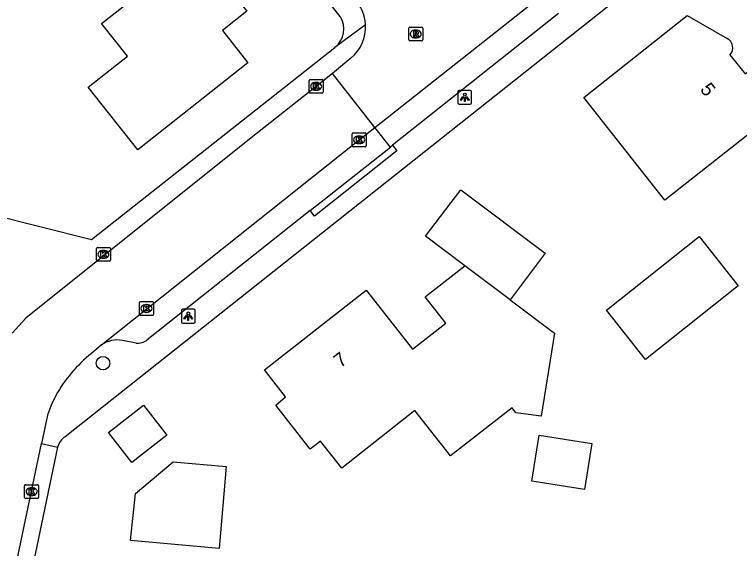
# Model space of a CAD drawing. Extents: x 159628 to 160723, y 388176 to 389416.
# Drawn here: x 159907.8 to 159959.9, y 388591.8 to 388630.2 of the extents above; entities that cross this region are included whole.
import ezdxf

# ---------------------------------------------------------------- set-up
doc = ezdxf.new("R2010")
doc.units = 0
for name, color, linetype in [('IMGEO_Boom', 7, 'Continuous'), ('IMGEO_Kolk', 7, 'Continuous'), ('IMGEO_Lichtpunt', 7, 'Continuous'), ('IMGEO_Pand', 7, 'Continuous'), ('IMGEO_Pand_nummerreeks', 7, 'Continuous'), ('IMGEO_Parkeervlak_open', 7, 'Continuous'), ('IMGEO_Rijbaan_lokaal_open', 7, 'Continuous'), ('IMGEO_Rioolput', 7, 'Continuous'), ('IMGEO_Voetpad_open', 7, 'Continuous')]:
    doc.layers.add(name, color=color, linetype=linetype)

msp = doc.modelspace()

# ---------------------------------------------------------------- linework, layer by layer
at = {"layer": 'IMGEO_Boom'}
msp.add_circle((159914.185, 388605.108), 0.489, dxfattribs=at)
at = {"layer": 'IMGEO_Kolk'}
for p, q in [((159929.006, 388624.603), (159929.006, 388625.455)), ((159929.081, 388625.529), (159929.933, 388625.529)), ((159930.007, 388625.455), (159930.007, 388624.603)), ((159929.494, 388625.309), (159929.519, 388625.309)), ((159929.933, 388624.529), (159929.081, 388624.529)), ((159929.517, 388624.749), (159929.492, 388624.749)), ((159932.102, 388620.76), (159932.102, 388621.612)), ((159932.177, 388621.686), (159933.029, 388621.686)), ((159932.59, 388621.466), (159932.615, 388621.466)), ((159933.103, 388621.612), (159933.103, 388620.76)), ((159933.029, 388620.686), (159932.177, 388620.686)), ((159932.613, 388620.906), (159932.588, 388620.906)), ((159913.713, 388612.516), (159913.713, 388613.368)), ((159913.788, 388613.442), (159914.64, 388613.442)), ((159914.714, 388613.368), (159914.714, 388612.516)), ((159914.201, 388613.222), (159914.226, 388613.222)), ((159914.64, 388612.442), (159913.788, 388612.442)), ((159914.224, 388612.662), (159914.199, 388612.662)), ((159916.81, 388608.621), (159916.81, 388609.473)), ((159916.885, 388609.547), (159917.737, 388609.547)), ((159917.298, 388609.327), (159917.323, 388609.327)), ((159917.811, 388609.473), (159917.811, 388608.621)), ((159917.321, 388608.767), (159917.296, 388608.767)), ((159917.737, 388608.547), (159916.885, 388608.547)), ((159908.55, 388595.44), (159908.55, 388596.292)), ((159908.625, 388596.366), (159909.477, 388596.366)), ((159909.551, 388596.292), (159909.551, 388595.44)), ((159909.038, 388596.146), (159909.063, 388596.146)), ((159909.477, 388595.366), (159908.625, 388595.366)), ((159909.061, 388595.586), (159909.036, 388595.586))]:
    msp.add_line(p, q, dxfattribs=at)
for points in [[(159929.006, 388624.603), (159929.006, 388625.455)], [(159929.081, 388625.529), (159929.933, 388625.529)], [(159930.007, 388625.455), (159930.007, 388624.603)], [(159929.327, 388625.229), (159929.45, 388625.229), (159929.45, 388625.078), (159929.58, 388625.229), (159929.744, 388625.229), (159929.598, 388625.078), (159929.751, 388624.829), (159929.599, 388624.829), (159929.514, 388624.993), (159929.45, 388624.926), (159929.45, 388624.829), (159929.327, 388624.829), (159929.327, 388625.229)], [(159929.933, 388624.529), (159929.081, 388624.529)], [(159932.102, 388620.76), (159932.102, 388621.612)], [(159932.177, 388621.686), (159933.029, 388621.686)], [(159932.423, 388621.386), (159932.546, 388621.386), (159932.546, 388621.235), (159932.676, 388621.386), (159932.84, 388621.386), (159932.694, 388621.235), (159932.847, 388620.986), (159932.695, 388620.986), (159932.61, 388621.15), (159932.546, 388621.083), (159932.546, 388620.986), (159932.423, 388620.986), (159932.423, 388621.386)], [(159933.103, 388621.612), (159933.103, 388620.76)], [(159933.029, 388620.686), (159932.177, 388620.686)], [(159913.713, 388612.516), (159913.713, 388613.368)], [(159913.788, 388613.442), (159914.64, 388613.442)], [(159914.714, 388613.368), (159914.714, 388612.516)], [(159914.034, 388613.142), (159914.157, 388613.142), (159914.157, 388612.991), (159914.287, 388613.142), (159914.451, 388613.142), (159914.305, 388612.991), (159914.458, 388612.742), (159914.306, 388612.742), (159914.221, 388612.906), (159914.157, 388612.839), (159914.157, 388612.742), (159914.034, 388612.742), (159914.034, 388613.142)], [(159914.64, 388612.442), (159913.788, 388612.442)], [(159916.81, 388608.621), (159916.81, 388609.473)], [(159916.885, 388609.547), (159917.737, 388609.547)], [(159917.131, 388609.247), (159917.254, 388609.247), (159917.254, 388609.096), (159917.384, 388609.247), (159917.548, 388609.247), (159917.402, 388609.096), (159917.555, 388608.847), (159917.403, 388608.847), (159917.318, 388609.011), (159917.254, 388608.944), (159917.254, 388608.847), (159917.131, 388608.847), (159917.131, 388609.247)], [(159917.811, 388609.473), (159917.811, 388608.621)], [(159917.737, 388608.547), (159916.885, 388608.547)], [(159908.55, 388595.44), (159908.55, 388596.292)], [(159908.625, 388596.366), (159909.477, 388596.366)], [(159909.551, 388596.292), (159909.551, 388595.44)], [(159908.871, 388596.066), (159908.994, 388596.066), (159908.994, 388595.915), (159909.124, 388596.066), (159909.288, 388596.066), (159909.142, 388595.915), (159909.295, 388595.666), (159909.143, 388595.666), (159909.058, 388595.83), (159908.994, 388595.763), (159908.994, 388595.666), (159908.871, 388595.666), (159908.871, 388596.066)], [(159909.477, 388595.366), (159908.625, 388595.366)]]:
    msp.add_lwpolyline(points, dxfattribs=at)
for centre, start, end in [((159929.083, 388625.453), 91.552, 178.448), ((159929.083, 388625.453), 91.552, 178.448), ((159929.931, 388625.453), 1.552, 88.448), ((159929.931, 388625.453), 1.552, 88.448), ((159929.083, 388624.605), 181.552, 268.448), ((159929.083, 388624.605), 181.552, 268.448), ((159929.931, 388624.605), 271.552, 358.448), ((159929.931, 388624.605), 271.552, 358.448), ((159932.179, 388621.61), 91.552, 178.448), ((159932.179, 388621.61), 91.552, 178.448), ((159933.027, 388621.61), 1.552, 88.448), ((159933.027, 388621.61), 1.552, 88.448), ((159932.179, 388620.762), 181.552, 268.448), ((159932.179, 388620.762), 181.552, 268.448), ((159933.027, 388620.762), 271.552, 358.448), ((159933.027, 388620.762), 271.552, 358.448), ((159913.79, 388613.366), 91.552, 178.448), ((159913.79, 388613.366), 91.552, 178.448), ((159914.638, 388613.366), 1.552, 88.448), ((159914.638, 388613.366), 1.552, 88.448), ((159913.79, 388612.518), 181.552, 268.448), ((159913.79, 388612.518), 181.552, 268.448), ((159914.638, 388612.518), 271.552, 358.448), ((159914.638, 388612.518), 271.552, 358.448), ((159916.887, 388609.471), 91.552, 178.448), ((159916.887, 388609.471), 91.552, 178.448), ((159917.735, 388609.471), 1.552, 88.448), ((159917.735, 388609.471), 1.552, 88.448), ((159916.887, 388608.623), 181.552, 268.448), ((159916.887, 388608.623), 181.552, 268.448), ((159917.735, 388608.623), 271.552, 358.448), ((159917.735, 388608.623), 271.552, 358.448), ((159908.627, 388596.29), 91.552, 178.448), ((159908.627, 388596.29), 91.552, 178.448), ((159909.475, 388596.29), 1.552, 88.448), ((159909.475, 388596.29), 1.552, 88.448), ((159908.627, 388595.442), 181.552, 268.448), ((159908.627, 388595.442), 181.552, 268.448), ((159909.475, 388595.442), 271.552, 358.448), ((159909.475, 388595.442), 271.552, 358.448)]:
    msp.add_arc(centre, 0.0765, start, end, dxfattribs=at)
for centre, major_axis, ratio, start_param, end_param in [((159929.493, 388625.029), (-0.387, 0.002), 0.722429, 4.712389, 7.853982), ((159929.518, 388625.029), (-0.39, 0.002), 0.717154, 1.570796, 4.712389), ((159932.589, 388621.186), (-0.387, 0.002), 0.722429, 4.712389, 7.853982), ((159932.614, 388621.186), (-0.39, 0.002), 0.717154, 1.570796, 4.712389), ((159914.2, 388612.942), (-0.387, 0.002), 0.722429, 4.712389, 7.853982), ((159914.225, 388612.942), (-0.39, 0.002), 0.717154, 1.570796, 4.712389), ((159917.297, 388609.047), (-0.387, 0.002), 0.722429, 4.712389, 7.853982), ((159917.322, 388609.047), (-0.39, 0.002), 0.717154, 1.570796, 4.712389), ((159909.037, 388595.866), (-0.387, 0.002), 0.722429, 4.712389, 7.853982), ((159909.062, 388595.866), (-0.39, 0.002), 0.717154, 1.570796, 4.712389)]:
    msp.add_ellipse(centre, major_axis=major_axis, ratio=ratio, start_param=start_param, end_param=end_param, dxfattribs=at)
at = {"layer": 'IMGEO_Lichtpunt'}
for p, q in [((159939.694, 388624.639), (159939.694, 388623.832)), ((159939.694, 388624.639), (159939.694, 388623.832)), ((159940.596, 388624.734), (159939.788, 388624.734)), ((159940.596, 388624.734), (159939.788, 388624.734)), ((159940.69, 388623.832), (159940.69, 388624.639)), ((159940.69, 388623.832), (159940.69, 388624.639)), ((159939.788, 388623.738), (159940.596, 388623.738)), ((159939.788, 388623.738), (159940.596, 388623.738)), ((159919.82, 388608.896), (159919.82, 388608.089)), ((159919.82, 388608.896), (159919.82, 388608.089)), ((159920.722, 388608.991), (159919.914, 388608.991)), ((159920.722, 388608.991), (159919.914, 388608.991)), ((159920.816, 388608.089), (159920.816, 388608.896)), ((159920.816, 388608.089), (159920.816, 388608.896)), ((159919.914, 388607.995), (159920.722, 388607.995)), ((159919.914, 388607.995), (159920.722, 388607.995))]:
    msp.add_line(p, q, dxfattribs=at)
for points in [[(159940.068, 388624.303), (159940.107, 388624.275), (159939.919, 388624.013), (159939.881, 388624.04), (159940.068, 388624.303)], [(159940.17, 388624.255), (159940.217, 388624.255), (159940.217, 388623.933), (159940.17, 388623.933), (159940.17, 388624.255)], [(159940.28, 388624.275), (159940.318, 388624.302), (159940.505, 388624.04), (159940.466, 388624.012), (159940.28, 388624.275)], [(159920.194, 388608.56), (159920.233, 388608.532), (159920.045, 388608.27), (159920.007, 388608.297), (159920.194, 388608.56)], [(159920.296, 388608.512), (159920.343, 388608.512), (159920.343, 388608.19), (159920.296, 388608.19), (159920.296, 388608.512)], [(159920.406, 388608.532), (159920.444, 388608.559), (159920.631, 388608.297), (159920.592, 388608.269), (159920.406, 388608.532)]]:
    msp.add_lwpolyline(points, dxfattribs=at)
for centre in [(159940.193, 388624.437), (159920.319, 388608.694)]:
    msp.add_circle(centre, 0.0994, dxfattribs=at)
for centre, start, end in [((159939.788, 388624.639), 90, 180), ((159939.788, 388624.639), 90, 180), ((159940.596, 388624.639), 0, 90), ((159940.596, 388624.639), 0, 90), ((159939.788, 388623.832), 180, 270), ((159939.788, 388623.832), 180, 270), ((159940.596, 388623.832), 270, 0), ((159940.596, 388623.832), 270, 360), ((159919.914, 388608.896), 90, 180), ((159919.914, 388608.896), 90, 180), ((159920.722, 388608.896), 0, 90), ((159920.722, 388608.896), 0, 90), ((159919.914, 388608.089), 180, 270), ((159919.914, 388608.089), 180, 270), ((159920.722, 388608.089), 270, 0), ((159920.722, 388608.089), 270, 360)]:
    msp.add_arc(centre, 0.0946, start, end, dxfattribs=at)
at = {"layer": 'IMGEO_Pand'}
for points in [[(159919.439, 388636.852), (159924.526, 388630.44), (159922.779, 388629.058), (159924.606, 388626.733), (159916.692, 388620.45), (159913.119, 388624.96), (159915.939, 388627.194), (159914.078, 388629.544), (159917.367, 388632.15), (159915.878, 388634.03), (159919.439, 388636.852)], [(159948.766, 388624.226), (159956.185, 388630.121), (159959.052, 388628.472)], [(159959.266, 388627.3), (159960.348, 388625.938), (159962.942, 388627.943), (159965.142, 388625.158), (159954.57, 388616.83), (159948.766, 388624.226)], [(159940.198, 388612.116), (159937.379, 388614.237), (159939.906, 388617.594), (159945.978, 388613.024), (159943.452, 388609.667)], [(159950.38, 388608.93), (159957.042, 388614.232), (159959.861, 388610.685), (159953.201, 388605.385), (159950.38, 388608.93)], [(159943.452, 388609.667), (159946.648, 388607.262), (159945.685, 388601.287), (159943.878, 388601.537), (159943.594, 388601.9), (159939.173, 388598.432), (159936.612, 388601.696), (159931.345, 388597.564), (159929.82, 388599.5), (159929.075, 388598.917), (159926.608, 388602.077), (159927.317, 388602.699), (159925.804, 388604.638), (159933.115, 388610.351), (159933.195, 388610.248), (159936.429, 388606.113), (159938.832, 388607.991), (159937.348, 388609.889), (159937.584, 388610.074), (159940.198, 388612.116)], [(159943.452, 388609.667), (159940.198, 388612.116)], [(159916.253, 388597.96), (159914.576, 388600.109), (159917.108, 388602.085), (159918.785, 388599.935), (159916.253, 388597.96)], [(159945.014, 388596.622), (159945.548, 388599.936), (159949.338, 388599.325), (159948.804, 388596.011), (159945.014, 388596.622)], [(159916.171, 388592.345), (159916.519, 388595.736), (159919.239, 388598.011), (159923.032, 388597.671), (159922.53, 388591.783), (159916.171, 388592.345)]]:
    msp.add_lwpolyline(points, dxfattribs=at)
msp.add_arc((159958.727, 388627.807), 0.74, 316.7507, 63.945, dxfattribs=at)
at = {"layer": 'IMGEO_Parkeervlak_open'}
msp.add_lwpolyline([(159934.849, 388620.662), (159933.737, 388622.071)], dxfattribs=at)
at = {"layer": 'IMGEO_Rijbaan_lokaal_open'}
for points in [[(159933.737, 388622.071), (159945.827, 388631.669)], [(159932.015, 388627.053), (159930.674, 388625.944)], [(159930.674, 388625.944), (159929.504, 388625.028), (159924.843, 388621.328), (159908.628, 388608.359), (159907.664, 388607.259)], [(159933.737, 388622.071), (159930.674, 388625.944)], [(159914.07, 388606.423), (159932.598, 388621.187), (159933.737, 388622.071)], [(159914.07, 388606.423), (159913.358, 388605.815)], [(159910.787, 388602.795), (159910.454, 388602.084), (159910.189, 388601.359), (159909.761, 388599.318)], [(159907.864, 388590.284), (159909.761, 388599.318)]]:
    msp.add_lwpolyline(points, dxfattribs=at)
for centre, radius, start, end in [((159930.139, 388629.304), 2.927, 3.1498, 45.0586), ((159930.144, 388629.299), 2.923, 309.8068, 3.2639), ((159920.072, 388597.495), 10.691, 128.9017, 150.2812)]:
    msp.add_arc(centre, radius, start, end, dxfattribs=at)
at = {"layer": 'IMGEO_Rioolput'}
for p, q in [((159936.169, 388628.37), (159936.169, 388629.222)), ((159936.244, 388629.296), (159937.096, 388629.296)), ((159936.657, 388629.076), (159936.682, 388629.076)), ((159937.17, 388629.222), (159937.17, 388628.37)), ((159936.68, 388628.516), (159936.655, 388628.516)), ((159937.096, 388628.296), (159936.244, 388628.296))]:
    msp.add_line(p, q, dxfattribs=at)
for points in [[(159936.169, 388628.37), (159936.169, 388629.222)], [(159936.244, 388629.296), (159937.096, 388629.296)], [(159937.17, 388629.222), (159937.17, 388628.37)], [(159936.758, 388628.994), (159936.506, 388628.996), (159936.506, 388628.596)], [(159936.506, 388628.596), (159936.63, 388628.596), (159936.63, 388628.758), (159936.641, 388628.758)], [(159936.684, 388628.915), (159936.63, 388628.915), (159936.63, 388628.834)], [(159936.63, 388628.834), (159936.682, 388628.834)], [(159936.688, 388628.729), (159936.759, 388628.596), (159936.899, 388628.596), (159936.834, 388628.722)], [(159937.096, 388628.296), (159936.244, 388628.296)]]:
    msp.add_lwpolyline(points, dxfattribs=at)
for centre, radius, start, end in [((159936.246, 388629.22), 0.0765, 91.552, 178.448), ((159936.246, 388629.22), 0.0765, 91.552, 178.448), ((159937.094, 388629.22), 0.0765, 1.552, 88.448), ((159937.094, 388629.22), 0.0765, 1.552, 88.448), ((159936.64, 388628.705), 0.0533, 26.0293, 88.6989), ((159936.666, 388629.023), 0.19, 274.7715, 282.9687), ((159936.69, 388628.819), 0.0964, 77.0061, 93.1865), ((159936.704, 388628.876), 0.0378, 276.6634, 79.6772), ((159936.757, 388628.884), 0.109, 350.3612, 89.416), ((159936.755, 388628.884), 0.112, 277.5842, 350.9817), ((159936.739, 388628.669), 0.108, 29.5134, 73.7905), ((159936.246, 388628.372), 0.0765, 181.552, 268.448), ((159936.246, 388628.372), 0.0765, 181.552, 268.448), ((159937.094, 388628.372), 0.0765, 271.552, 358.448), ((159937.094, 388628.372), 0.0765, 271.552, 358.448)]:
    msp.add_arc(centre, radius, start, end, dxfattribs=at)
for centre, major_axis, ratio, start_param, end_param in [((159936.656, 388628.796), (-0.387, 0.002), 0.722429, 4.712389, 7.853982), ((159936.681, 388628.796), (-0.39, 0.002), 0.717154, 1.570796, 4.712389)]:
    msp.add_ellipse(centre, major_axis=major_axis, ratio=ratio, start_param=start_param, end_param=end_param, dxfattribs=at)
at = {"layer": 'IMGEO_Voetpad_open'}
for points in [[(159931.239, 388630.067), (159909.982, 388656.93)], [(159955.063, 388634.415), (159911.466, 388599.82)], [(159946.926, 388630.28), (159935.008, 388620.788)], [(159933.062, 388629.465), (159930.846, 388627.835)], [(159906.097, 388615.825), (159913.35, 388614.019), (159930.846, 388627.835)], [(159935.008, 388620.788), (159935.318, 388620.396), (159929.383, 388615.697), (159929.073, 388616.089)], [(159934.849, 388620.662), (159935.008, 388620.788)], [(159929.073, 388616.089), (159934.849, 388620.662)], [(159929.073, 388616.089), (159917.343, 388606.776)], [(159916.56, 388606.554), (159915.575, 388606.751)], [(159909.761, 388599.318), (159910.917, 388599.067)], [(159910.917, 388599.067), (159890.615, 388501.836)]]:
    msp.add_lwpolyline(points, dxfattribs=at)
for centre, radius, start, end in [((159929.847, 388629.162), 1.661, 306.9875, 33.0405), ((159915.235, 388604.693), 2.086, 80.6247, 123.9649), ((159916.688, 388607.595), 1.049, 263.0051, 308.6537), ((159912.161, 388598.737), 1.287, 122.6791, 165.1305)]:
    msp.add_arc(centre, radius, start, end, dxfattribs=at)

# ---------------------------------------------------------------- texts
at = {"layer": 'IMGEO_Pand_nummerreeks'}
for s, rotation, p in [('5', 308.4643, (159957.067, 388624.794)), ('7', 38.005, (159931.262, 388604.74))]:
    msp.add_text(s, height=1, rotation=rotation, dxfattribs=at).set_placement(p)

doc.saveas('drawing.dxf')
